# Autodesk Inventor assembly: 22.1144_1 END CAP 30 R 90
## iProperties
Created: 2012-08
Part Number: 22.1144_1 END CAP 30 R 90
Document SubType Name: Assembly
Designer: Administrator
Mass: 1.99651 g
Surface Area: 23.7106 cm^2
Volume: 1.98899 cm^3
Density: 1.00378 g/cm^3
Author: Administrator
